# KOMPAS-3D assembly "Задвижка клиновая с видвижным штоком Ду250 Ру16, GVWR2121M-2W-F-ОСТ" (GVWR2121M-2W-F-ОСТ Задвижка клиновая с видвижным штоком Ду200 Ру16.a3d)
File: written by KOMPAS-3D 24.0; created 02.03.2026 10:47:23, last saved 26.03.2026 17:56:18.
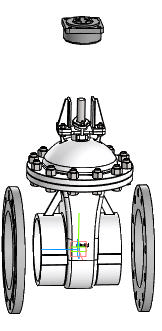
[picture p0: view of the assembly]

Document properties: Автор: R2D2; Полное имя файла: E:\Работа\Зайцев\GVWR2121M-2W-F-ОСТ Задвижка клиновая с видвижным штоком Ду50-300 Ру16\DN250\Исходные материалы\GVWR2121M-2W-F-ОСТ Задвижка клиновая с видвижным штоком Ду250 Ру16.a3d

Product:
- Component [detail]: AS 1110 - M10 x 35  | qty 4  | pos. 2  | Масса: 0.032708; Комментарий: Болты и винты   шестигранные точные   метрические ISO; Автор: R2D2; additional columns: Сталь, мягкая; source file: AS 1110 - M10 x 35 AS 1110 - M10 x 35.m3d
- Component [detail]: ANSI B18.2.4.2M - M10x1,5 - 16  | designation ANSI B18.2.4.2M - M10x1,5  | qty 4  | pos. 3  | Масса: 0.012122; Комментарий: Типы метрических   шестигранных гаек   2; Автор: R2D2; additional columns: Сталь, мягкая; source file: ANSI B18.2.4.2M - M10x1,5 ANSI B18.2.4.2M - M10x1,5 - 16.m3d
- Component [detail]: ANSI B18.2.4.2M - M8x1,25 - 13  | designation ANSI B18.2.4.2M - M8x1,25  | qty 1  | pos. 4  | Масса: 0.006562; Комментарий: Типы метрических   шестигранных гаек   2; Автор: R2D2; additional columns: Сталь, мягкая; source file: ANSI B18.2.4.2M - M8x1,25 ANSI B18.2.4.2M - M8x1,25 - 13.m3d
- Component [detail]: ANSI B18.2.4.2M - M20x2,5 - 30  | designation ANSI B18.2.4.2M - M20x2,5  | qty 12  | pos. 5  | Масса: 0.08464; Комментарий: Типы метрических   шестигранных гаек   2; Автор: R2D2; additional columns: Сталь, мягкая; source file: ANSI B18.2.4.2M - M20x2,5 ANSI B18.2.4.2M - M20x2,5 - 30.m3d
- Component [detail]: AS 1110 - M20 x 70  | qty 12  | pos. 6  | Масса: 0.248341; Комментарий: Болты и винты   шестигранные точные   метрические ISO; Автор: R2D2; additional columns: Сталь, мягкая; source file: AS 1110 - M20 x 70 AS 1110 - M20 x 70.m3d
- Component [detail]: Деталь1  | qty 1  | pos. 7  | Масса: 135.40649; Автор: R2D2; additional columns: Типовые; source file: 2.m3d
- Component [detail]: ANSI B18.2.4.2M - M8x1,25 - 13  | designation ANSI B18.2.4.2M - M8x1,25-01  | qty 1  | pos. 8  | Масса: 0.006562; Комментарий: Типы метрических   шестигранных гаек   2; Автор: R2D2; additional columns: Сталь, мягкая; source file: ANSI B18.2.4.2M - M8x1,25 ANSI B18.2.4.2M - M8x1,25 - 13.m3d
- Component [detail]: Фланец  | qty 2  | pos. 7  | Масса: 16.336215; Автор: R2D2; additional columns: Типовые; source file: Фланец DN250 Pn16 b30.m3d
- Component [assembly]: DN250_3D_STEP  | designation Сборка  | qty 1  | pos. 9  | Масса: 5.393712; Автор: R2D2; source file: Фланец Б.a3d
- Part/product: Задвижка клиновая с видвижным штоком Ду250 Ру16  | designation GVWR2121M-2W-F-ОСТ
    Масса: 107
    Раздел спецификации: Прочие изделия
    Примечание: D040-08597

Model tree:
1. Массив по концентрической сетке:1  (labels: Грань.Твердое тело1)  (12 pattern instances)
     Шаг 2 = 360
2. Массив по сетке:1  (with: Грань.Элемент вращения:1, Грань.Элемент выдавливания:5, Грань.Элемент выдавливания:7)  (labels: Грань.Твердое тело1; Грань.Solid1)  (4 pattern instances)
     Шаг 1 = 50; Угол раствора = 90; Шаг 2 = 120; Ориентация = 2; Расстояние = -225; Ориентация = 2; Расстояние = -767

Referenced files in E:\Работа\Зайцев\GVWR2121M-2W-F-ОСТ Задвижка клиновая с видвижным штоком Ду50-300 Ру16\DN250\Исходные материалы\: AS 1110 - M10 x 35 AS 1110 - M10 x 35.m3d, ANSI B18.2.4.2M - M10x1,5 ANSI B18.2.4.2M - M10x1,5 - 16.m3d, ANSI B18.2.4.2M - M8x1,25 ANSI B18.2.4.2M - M8x1,25 - 13.m3d, ANSI B18.2.4.2M - M20x2,5 ANSI B18.2.4.2M - M20x2,5 - 30.m3d, AS 1110 - M20 x 70 AS 1110 - M20 x 70.m3d, 2.m3d, Фланец DN250 Pn16 b30.m3d, Фланец Б.a3d
Referenced files in E:\Работа\Зайцев\GVWR3131M-2W-F-S Задвижка клиновая с выдвижным штоком DN.ru Ду50-200 Ру63\DN200\исходные материалы\: ANSI B18.2.4.2M - M20x2,5 ANSI B18.2.4.2M - M20x2,5 - 30.m3d, AS 1110 - M20 x 70 AS 1110 - M20 x 70.m3d, ANSI B18.2.4.2M - M10x1,5 ANSI B18.2.4.2M - M10x1,5 - 16.m3d, AS 1110 - M10 x 35 AS 1110 - M10 x 35.m3d
Referenced files in E:\Работа\Зайцев\GVWR2626M-2W-F-S Задвижка клиновая с выдвижным штоком DN.ru Ду50-300 Ру16\DN250\исходные материалы\: Фланец DN250 Pn16 b30.m3d
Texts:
  Программные изделия  и базы данных
  ANSI B18.2.4.2M - M10x1,5
  ANSI B18.2.4.2M - M8x1,25
  ANSI B18.2.4.2M - M20x2,5
  ANSI B18.2.4.2M - M8x1,25 - 01
  ANSI B18.2.4.2M - M8x1,25-01
  GVWR2121M-2W-F-ОСТ
  AS 1110 - M10 x 35 AS 1110 - M10 x 35 (1)
  ANSI B18.2.4.2M - M10x1,5 ANSI B18.2.4.2M - M10x1,5 - 16 (1)
  ANSI B18.2.4.2M - M8x1,25 ANSI B18.2.4.2M - M8x1,25 - 13
  ANSI B18.2.4.2M - M20x2,5 ANSI B18.2.4.2M - M20x2,5 - 30 (1)
  AS 1110 - M20 x 70 AS 1110 - M20 x 70 (1)
  Деталь1 Деталь1
  ANSI B18.2.4.2M - M20x2,5 ANSI B18.2.4.2M - M20x2,5 - 30 (2)
  AS 1110 - M20 x 70 AS 1110 - M20 x 70 (2)
  ANSI B18.2.4.2M - M20x2,5 ANSI B18.2.4.2M - M20x2,5 - 30 (3)
  AS 1110 - M20 x 70 AS 1110 - M20 x 70 (3)
  ANSI B18.2.4.2M - M20x2,5 ANSI B18.2.4.2M - M20x2,5 - 30 (4)
  AS 1110 - M20 x 70 AS 1110 - M20 x 70 (4)
  ANSI B18.2.4.2M - M20x2,5 ANSI B18.2.4.2M - M20x2,5 - 30 (5)
  AS 1110 - M20 x 70 AS 1110 - M20 x 70 (5)
  ANSI B18.2.4.2M - M20x2,5 ANSI B18.2.4.2M - M20x2,5 - 30 (6)
  AS 1110 - M20 x 70 AS 1110 - M20 x 70 (6)
  ANSI B18.2.4.2M - M20x2,5 ANSI B18.2.4.2M - M20x2,5 - 30 (7)
  AS 1110 - M20 x 70 AS 1110 - M20 x 70 (7)
  ANSI B18.2.4.2M - M20x2,5 ANSI B18.2.4.2M - M20x2,5 - 30 (8)
  AS 1110 - M20 x 70 AS 1110 - M20 x 70 (8)
  ANSI B18.2.4.2M - M20x2,5 ANSI B18.2.4.2M - M20x2,5 - 30 (9)
  AS 1110 - M20 x 70 AS 1110 - M20 x 70 (9)
  ANSI B18.2.4.2M - M20x2,5 ANSI B18.2.4.2M - M20x2,5 - 30 (10)
  AS 1110 - M20 x 70 AS 1110 - M20 x 70 (10)
  ANSI B18.2.4.2M - M20x2,5 ANSI B18.2.4.2M - M20x2,5 - 30 (11)
  AS 1110 - M20 x 70 AS 1110 - M20 x 70 (11)
  ANSI B18.2.4.2M - M20x2,5 ANSI B18.2.4.2M - M20x2,5 - 30 (12)
  AS 1110 - M20 x 70 AS 1110 - M20 x 70 (12)
  ANSI B18.2.4.2M - M10x1,5 ANSI B18.2.4.2M - M10x1,5 - 16 (2)
  AS 1110 - M10 x 35 AS 1110 - M10 x 35 (2)
  ANSI B18.2.4.2M - M10x1,5 ANSI B18.2.4.2M - M10x1,5 - 16 (3)
  AS 1110 - M10 x 35 AS 1110 - M10 x 35 (3)
  ANSI B18.2.4.2M - M10x1,5 ANSI B18.2.4.2M - M10x1,5 - 16 (4)
  AS 1110 - M10 x 35 AS 1110 - M10 x 35 (4)
  ANSI B18.2.4.2M - M8x1,25-01 ANSI B18.2.4.2M - M8x1,25 - 13
  Фланец (1)
  Фланец (2)
  Сборка DN250_3D_STEP
  Ось Y.Начало координат
  Ось Z.Начало координат
  Плоскость ZY.Начало координат
  Плоскость ZX.Начало координат
  Плоскость XY.Начало координат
